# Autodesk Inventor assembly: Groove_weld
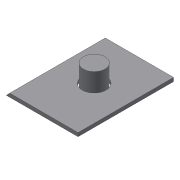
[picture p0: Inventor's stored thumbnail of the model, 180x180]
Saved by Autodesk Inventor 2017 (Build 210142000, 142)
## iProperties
Created: 2016-08
Part Number: Groove_weld
Document SubType Name: Weldment
Designer: Gaurav
Weld Material: Welded Aluminum-6061
Author: Gaurav
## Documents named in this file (3)
- D:\My Data\Books_Final Books\Autodesk Inventor 2015_resources\Chapter 11\Groove_weld.iam
- D:\My Data\Books_Final Books\Autodesk Inventor 2015_resources\Chapter 11\Plate.ipt
- D:\My Data\Books_Final Books\Autodesk Inventor 2015_resources\Chapter 11\Rod.ipt
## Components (2 placed, 2 different names)
1. Plate:1 — Mate:1, Flush:3
2. Rod:1 — Mate:1, Flush:3
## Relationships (2: Mate 1, Flush 1)
- Mate:1: Plate:1 ↔ Rod:1
- Flush:3: Plate:1 ↔ Rod:1
